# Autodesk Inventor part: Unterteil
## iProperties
Created: 2005-01
Part Number: Unterteil
Material: Standard
Document SubType Name: Modeling
Designer: ap
Manufacturer: Standard
Standards Organization: Custom
Author: ap
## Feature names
1. Basis1
